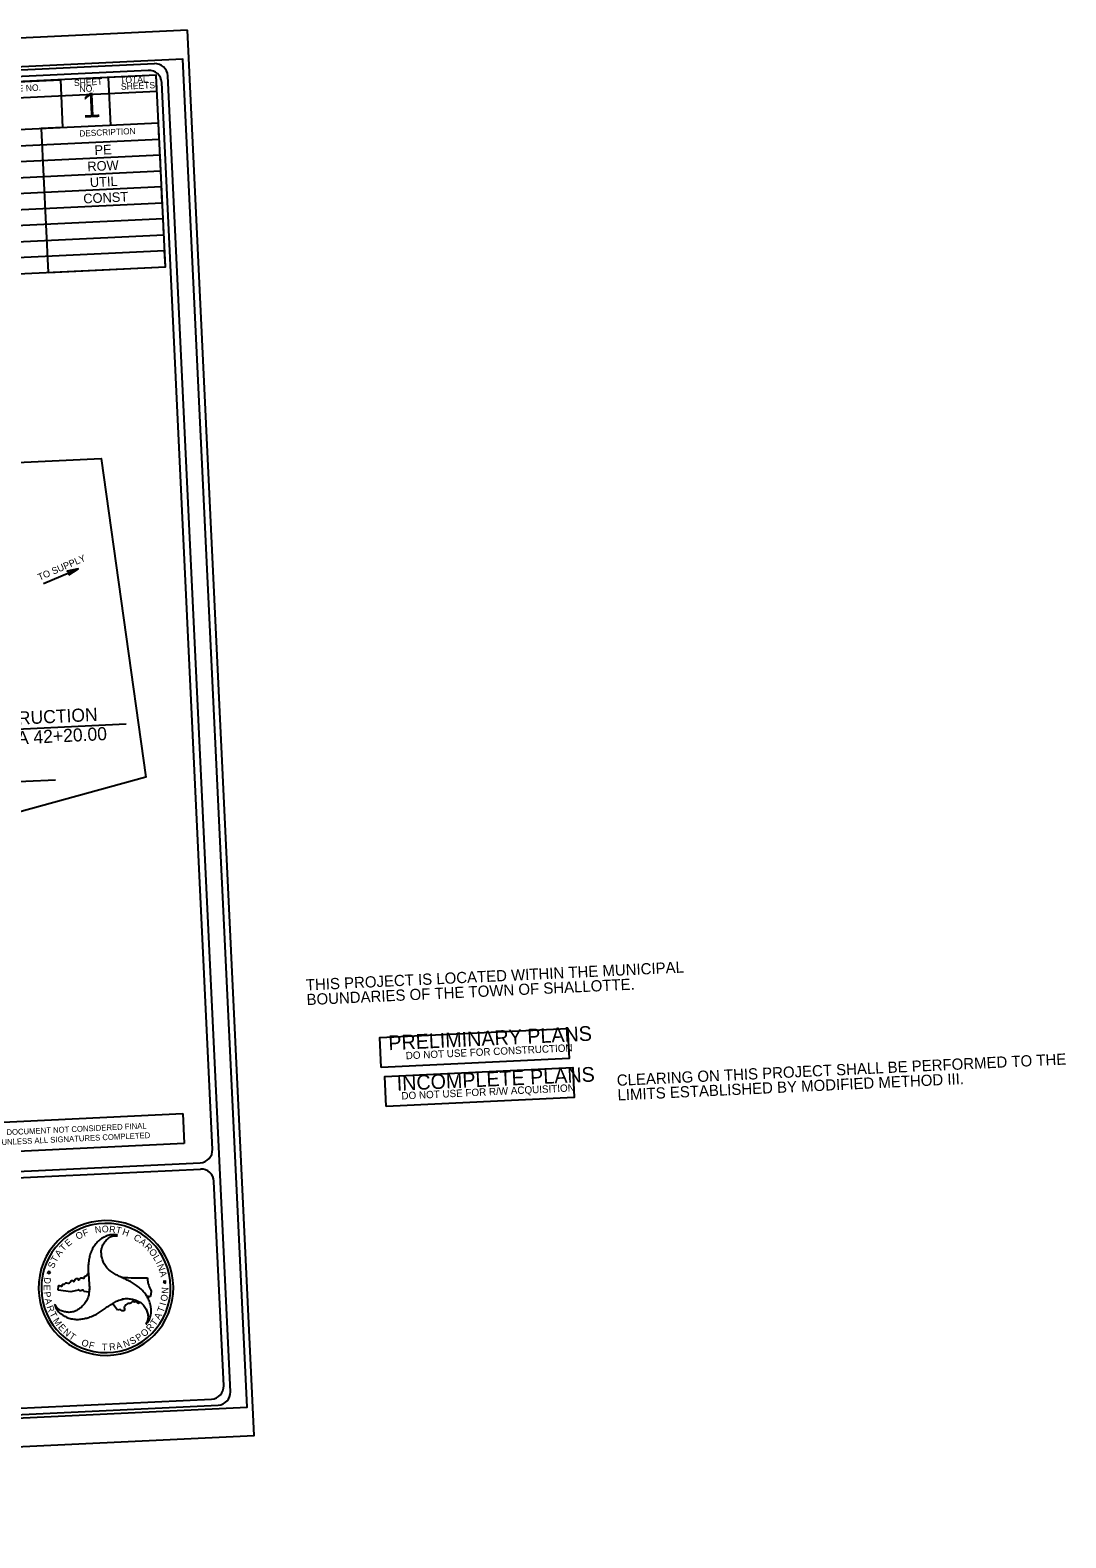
# Model space of a CAD drawing. Extents: x 2170913 to 2188101, y 74009 to 87693.
# Drawn here: x 2182226 to 2188101, y 74009 to 82562 of the extents above; entities that cross this region are included whole.
import ezdxf

# ---------------------------------------------------------------- set-up
doc = ezdxf.new("R2010")
doc.units = 0
for name, color, linetype in [('CTL Primary Horizontal and Vertical CELL', 7, 'Continuous'), ('CTL Primary Horizontal CELL', 7, 'Continuous'), ('CTL Primary Horizontal Cogo Comment', 7, 'Continuous'), ('CTL Primary Horizontal Cogo Number', 7, 'Continuous'), ('Exist Other Culture Sign', 7, 'Continuous'), ('Exist Other Culture Sign Cogo Point CELL', 7, 'Continuous'), ('Exist Property Iron Pin CELL', 7, 'Continuous'), ('Exist Property Iron Pin Cogo Number', 7, 'Continuous'), ('Exist Structure Minor Pipes HDPE 30 Inch', 7, 'Continuous'), ('Exist Utilities Other Traffic Signal Box CELL', 7, 'Continuous')]:
    doc.layers.add(name, color=color, linetype=linetype)

msp = doc.modelspace()

# ---------------------------------------------------------------- linework, layer by layer
at = {"layer": 'CTL Primary Horizontal and Vertical CELL'}
msp.add_lwpolyline([(2183118, 82562.2), (2170912.8, 81981.8), (2171291.9, 74009.3), (2183497.2, 74589.8)], close=True, dxfattribs=at)
at = {"layer": 'CTL Primary Horizontal CELL'}
for p, q in [((2182027.1, 76365.6), (2183092.5, 76416.3)), ((2183092.5, 76416.2), (2183100.6, 76245.8)), ((2183100.6, 76245.9), (2182035.2, 76195.3))]:
    msp.add_line(p, q, dxfattribs=at)
at = {"layer": 'CTL Primary Horizontal Cogo Comment'}
msp.add_lwpolyline([(2171378.4, 74176.5), (2183456.8, 74750.8), (2183093.1, 82397.9), (2171014.8, 81823.6)], close=True, dxfattribs=at)
at = {"layer": 'CTL Primary Horizontal Cogo Number'}
for p, q in [((2172899.3, 75647.6), (2183191.1, 76137)), ((2182067.8, 76047.3), (2183192.8, 76100.8)), ((2182722.4, 75725.3), (2182721.6, 75724.6)), ((2182722.4, 75725.3), (2182721.6, 75724.6)), ((2182330.8, 75517.3), (2182333.1, 75523.2)), ((2182333.1, 75523.2), (2182334.9, 75516.9)), ((2182329.1, 75513.4), (2182324.1, 75517.8)), ((2182324.1, 75517.8), (2182330.8, 75517.3)), ((2182326.7, 75507.3), (2182329.1, 75513.4)), ((2182332.1, 75510.8), (2182326.7, 75507.3)), ((2182337.2, 75506.4), (2182332.1, 75510.8)), ((2182334.9, 75516.9), (2182341.4, 75516.4)), ((2182341.4, 75516.4), (2182335.7, 75512.9)), ((2182335.7, 75512.9), (2182337.2, 75506.4)), ((2182384.7, 75413.8), (2182387.5, 75436.7)), ((2182743.3, 75487.8), (2182743.3, 75487.8)), ((2182987.6, 75463.6), (2182981, 75464.2)), ((2182981, 75464.2), (2182986.1, 75459.9)), ((2182986.1, 75459.9), (2182983.6, 75453.7)), ((2182983.6, 75453.7), (2182989.1, 75457.1)), ((2182990.1, 75469.6), (2182987.6, 75463.6)), ((2182989.1, 75457.1), (2182994, 75452.8)), ((2182991.9, 75463.3), (2182990.1, 75469.6)), ((2182998.3, 75462.9), (2182991.9, 75463.3)), ((2182992.7, 75459.3), (2182998.3, 75462.9)), ((2182994, 75452.8), (2182992.7, 75459.3)), ((2182456.8, 75404.9), (2182384.7, 75413.8)), ((2182499.3, 75413.6), (2182456.8, 75404.9)), ((2182560.9, 75403.3), (2182530.7, 75406.2)), ((2183037.4, 75394.5), (2183037.4, 75394.5)), ((2182721.9, 75300.5), (2182692.9, 75337.9)), ((2182692.9, 75337.9), (2182692.9, 75337.9))]:
    msp.add_line(p, q, dxfattribs=at)
for points in [[(2182931, 82371.7), (2172204.2, 81861.7)], [(2182896.4, 82333.7), (2172604.7, 81844.3)], [(2180952.5, 82121.5), (2182945.6, 82216.3), (2182941.3, 82306.9), (2180948.2, 82212)], [(2181220, 82225.1), (2182397.8, 82281), (2182410.6, 82009.3), (2182289.6, 82003.5), (2182328.4, 81188.1), (2182993, 81219.7), (2182941.3, 82306.9), (2182669.5, 82294), (2182682.5, 82022.2)], [(2183361.9, 74837.6), (2183006.9, 82302.7)], [(2183260.2, 76212.8), (2182972.4, 82264.8)], [(2180965.4, 81849.6), (2182958.5, 81944.4), (2182954.2, 82035.1), (2180961.1, 81940.3)], [(2180974, 81668.5), (2182967.1, 81763.3), (2182962.8, 81853.8), (2180969.7, 81759.1)], [(2180982.6, 81487.4), (2182975.8, 81582.1), (2182971.5, 81672.7), (2180978.3, 81577.9)], [(2180991.3, 81306.1), (2182984.4, 81400.9), (2182980.1, 81491.4), (2180987, 81396.7)], [(2180999.9, 81125), (2182993, 81219.7), (2182988.7, 81310.3), (2180995.6, 81215.6)], [(2183323.9, 74872.1), (2183268.8, 76031.7)], [(2172566.2, 74251.5), (2183292.9, 74761.6)], [(2182129.9, 74742.7), (2183254.9, 74796.2)]]:
    msp.add_lwpolyline(points, dxfattribs=at)
for centre, radius, start, end in [((2182934.4, 82299.6), 72.6, 2.72267, 92.72267), ((2182899.9, 82261.7), 72.6, 2.72267, 92.72267), ((2183187.7, 76209.8), 72.6, 272.72267, 2.72267), ((2183196.3, 76028.6), 72.6, 2.72267, 92.72267), ((2182656.3, 75426.8), 382.5, 355.1438, 175.1438), ((2182656.3, 75426.8), 366.6, 355.1438, 175.1438), ((2182656.3, 75426.8), 382.5, 175.1438, 355.1438), ((2182656.3, 75426.8), 366.6, 175.1438, 355.1438), ((2182874.8, 77500.3), 2016.7, 260.82229, 260.92189), ((2182874.8, 77500.3), 2016.7, 266.26134, 270.46736), ((2183251.5, 74869), 72.6, 272.72267, 2.72267), ((2183289.4, 74834.5), 72.6, 272.72267, 2.72267)]:
    msp.add_arc(centre, radius, start, end, dxfattribs=at)
for points in [[(2182721.6, 75724.6), (2182713.2, 75727.6), (2182687.8, 75728.7), (2182661.4, 75722.7), (2182659, 75721.6), (2182645.6, 75715.9), (2182631, 75706.9), (2182608.7, 75689.1), (2182590.8, 75666.4), (2182583.6, 75656.7), (2182577.9, 75644.4), (2182567.2, 75618.2), (2182560.6, 75592.6), (2182556.3, 75562.4), (2182554.5, 75535.7), (2182556.6, 75508.1), (2182559, 75480.2), (2182560.7, 75453.2), (2182562.1, 75425.5), (2182559.9, 75398.2), (2182559.6, 75395.9), (2182552.2, 75367.3), (2182538.3, 75342.8), (2182521.4, 75322.8), (2182511.6, 75313.7), (2182498, 75304.8), (2182490.3, 75299.7), (2182472.3, 75292.4), (2182445.6, 75288.5), (2182420.2, 75292.1), (2182398.1, 75299.8), (2182379.3, 75314.2), (2182365.2, 75333.9)], [(2182882, 75220.7), (2182888.4, 75226.3), (2182902.3, 75247.7), (2182910.3, 75273.7), (2182910.9, 75276.3), (2182912.3, 75290.8), (2182911.9, 75308), (2182907.9, 75336.2), (2182896.8, 75362.9), (2182892.2, 75374.1), (2182884.3, 75385.4), (2182867.1, 75407.6), (2182848.3, 75426.2), (2182824.2, 75444.9), (2182801.9, 75459.6), (2182776.9, 75472), (2182751.7, 75483.7), (2182727.7, 75495.6), (2182702.5, 75508.4), (2182680.2, 75523.9), (2182678.4, 75525.5), (2182657, 75546.2), (2182642.9, 75570.5), (2182633.8, 75595.1), (2182631.3, 75607.9), (2182630.4, 75624.3), (2182629.5, 75633.7), (2182632.5, 75652.7), (2182642.3, 75678), (2182658, 75697.9), (2182675.8, 75713.1), (2182697.9, 75722.2), (2182721.6, 75724.6), (2182722.4, 75725.3)], [(2182387.5, 75436.7), (2182386.8, 75438.9), (2182390.9, 75441), (2182401.3, 75435.7), (2182407.1, 75439.9), (2182407.2, 75444.5), (2182411.9, 75448.8), (2182419.1, 75446.7), (2182426.5, 75454.6), (2182432.8, 75455.6), (2182445.6, 75454.5), (2182462.2, 75468.5), (2182468.7, 75468.9), (2182469.9, 75464.7), (2182473.8, 75463.6), (2182481.5, 75475.7), (2182483.3, 75477.3), (2182495.7, 75481.1), (2182498.7, 75478.5), (2182499.1, 75472.8), (2182500.7, 75471.5), (2182504.9, 75474), (2182510.8, 75480.4), (2182521, 75484.6), (2182532.1, 75482.3), (2182534.8, 75491.3), (2182548.6, 75499), (2182551.8, 75504.1), (2182552.9, 75509.4)], [(2182556.5, 75508.8), (2182556.6, 75508.1), (2182559, 75480.2), (2182560.7, 75453.2), (2182562.1, 75425.5), (2182560.8, 75403.3)], [(2182889.7, 75378.4), (2182884.3, 75385.4), (2182867.1, 75407.6), (2182848.3, 75426.2), (2182824.2, 75444.9), (2182801.9, 75459.6), (2182776.9, 75472), (2182751.7, 75483.7), (2182743.3, 75487.8)], [(2182891.2, 75483.5), (2182894.4, 75457.7), (2182905.2, 75426.6), (2182912.4, 75409.5), (2182911, 75395.4), (2182906.3, 75378.8), (2182889.9, 75378.5)], [(2182365.2, 75333.9), (2182367.2, 75325.1), (2182378.8, 75302.5), (2182397.1, 75282.5), (2182399.2, 75281.2), (2182411, 75272.1), (2182426.1, 75264.2), (2182452.7, 75253.5), (2182481, 75249.7), (2182493.1, 75248.1), (2182507.2, 75249.5), (2182534.6, 75253.3), (2182560, 75260.1), (2182588.5, 75271.7), (2182612.2, 75283.4), (2182635.4, 75299.1), (2182658.2, 75315.2), (2182680.8, 75330), (2182704.3, 75345), (2182728.9, 75356.9), (2182731.5, 75357.7), (2182760, 75365.8), (2182787.8, 75365.9), (2182813.3, 75361.5), (2182826.5, 75357.5), (2182840.6, 75349.8), (2182849.4, 75346), (2182864.5, 75333.9), (2182881, 75312.8), (2182890.6, 75289.2), (2182895, 75266), (2182891.9, 75242.5), (2182882, 75220.7)], [(2182530.7, 75406.2), (2182528.3, 75412), (2182522.5, 75414.2), (2182514.3, 75410.6), (2182508.3, 75411.5), (2182502.2, 75416.8), (2182499.3, 75413.6)], [(2182692.9, 75337.9), (2182704.3, 75345), (2182728.9, 75356.9), (2182731.5, 75357.7), (2182760, 75365.8), (2182787.8, 75365.9), (2182813.3, 75361.5), (2182826.5, 75357.5), (2182840.6, 75349.8), (2182848.8, 75346.2)], [(2182848.7, 75346.1), (2182844.6, 75339.7), (2182838.8, 75339.7), (2182829.4, 75348.6), (2182816.9, 75347.2), (2182811.5, 75350.9), (2182807.8, 75351.3), (2182797.9, 75340.9), (2182785.5, 75339.2), (2182764.5, 75326.4), (2182759.7, 75318.2), (2182759.6, 75299.8), (2182754.5, 75296.6), (2182748.7, 75298), (2182736.9, 75303.8), (2182721.9, 75300.5)]]:
    msp.add_spline(points, degree=3, dxfattribs=at)
at = {"layer": 'Exist Other Culture Sign'}
msp.add_lwpolyline([(2184246.5, 76457), (2184238.4, 76627.3), (2185303.9, 76678), (2185312, 76507.7)], close=True, dxfattribs=at)
at = {"layer": 'Exist Property Iron Pin CELL'}
for p, q in [((2182301.7, 79422.8), (2182498.3, 79506.7)), ((2182770.5, 78624.8), (2181526.2, 78565.6)), ((2182369.8, 78308.4), (2180865.5, 78236.8))]:
    msp.add_line(p, q, dxfattribs=at)
at = {"layer": 'Exist Property Iron Pin Cogo Number'}
msp.add_lwpolyline([(2182445.3, 79472.9), (2182498.3, 79506.7), (2182436.6, 79492.7), (2182448.2, 79485.7)], close=True, dxfattribs=at)
at = {"layer": 'Exist Structure Minor Pipes HDPE 30 Inch'}
msp.add_lwpolyline([(2177668.6, 79896.6), (2182629.7, 80132.5), (2182882.8, 78325.4), (2178890.9, 77226), (2178290.9, 78673.1), (2177852.1, 79004.7), (2177687.9, 79128.8)], close=True, dxfattribs=at)
at = {"layer": 'Exist Utilities Other Traffic Signal Box CELL'}
msp.add_lwpolyline([(2184217.5, 76677.7), (2184209.4, 76848.1), (2185274.8, 76898.7), (2185282.9, 76728.4)], close=True, dxfattribs=at)

# ---------------------------------------------------------------- texts
at = {"layer": 'CTL Primary Horizontal CELL'}
for s, p in [('UNLESS ALL SIGNATURES COMPLETED', (2182064.6, 76237.4)), ('DOCUMENT NOT CONSIDERED FINAL', (2182092.6, 76293.6))]:
    msp.add_text(s, height=32.652, rotation=2.72267, dxfattribs=at).set_placement(p)
at = {"layer": 'CTL Primary Horizontal Cogo Number'}
for s, height, rotation, p in [('SHEET', 36.28, 2.72267, (2182475.4, 82244.7)), ('TOTAL', 36.28, 2.72267, (2182737.6, 82259.8)), ('STATE PROJECT REFERENCE NO.', 36.278, 2.72267, (2181480.6, 82181.1)), ('NO.', 36.28, 2.72267, (2182507.1, 82210.4)), ('1', 140.4, 2.72267, (2182523.2, 82064.4)), ('SHEETS', 36.28, 2.72267, (2182741.8, 82223.7)), ('DESCRIPTION', 34.829, 2.72267, (2182506.4, 81958.2)), ('N', 38.2, 8.12757, (2182595.5, 75736.9)), ('O', 38.2, 0.62947, (2182632.4, 75742)), ('R', 38.1, 354.01954, (2182672.7, 75742.4)), ('E', 38, 39.30074, (2182441.7, 75658.8)), ('O', 38.2, 27.36136, (2182496.1, 75699)), ('F', 38.2, 20.21452, (2182532, 75717.4)), ('T', 38.2, 347.36991, (2182709.1, 75738.6)), ('H', 38.1, 340.28519, (2182745.4, 75730.2)), ('C', 38, 327.94284, (2182809.2, 75703.6)), ('A', 38.1, 320.44581, (2182841.3, 75683.2)), ('T', 38.2, 60.52389, (2182373.6, 75568)), ('A', 38.3, 53.47158, (2182392.4, 75600.2)), ('T', 38, 46.41636, (2182415.9, 75631.9)), ('R', 38.1, 314.08186, (2182871.5, 75658.4)), ('O', 38.2, 306.96226, (2182896.9, 75632.1)), ('L', 38, 300.72858, (2182921.3, 75599.6)), ('S', 38.1, 66.90005, (2182359.3, 75534.6)), ('I', 38.2, 296.73924, (2182937.5, 75571)), ('N', 38.1, 291.03913, (2182945.6, 75554.2)), ('E', 38, 269.28469, (2182302.6, 75445.5)), ('D', 38.1, 262.9968, (2182307.6, 75489)), ('A', 38.1, 283.60716, (2182958.8, 75519.2)), ('P', 38.1, 276.81708, (2182302.9, 75404)), ('A', 38.1, 283.40965, (2182307.7, 75363.6)), ('O', 38, 80.10391, (2183002, 75348.3)), ('N', 38.1, 87.35193, (2183009.5, 75393.7)), ('R', 38.1, 290.47829, (2182318.7, 75319.7)), ('T', 38.1, 297.12882, (2182333.8, 75280.5)), ('A', 38.2, 62.23396, (2182960.2, 75244)), ('T', 38.1, 69.31838, (2182980.8, 75284.2)), ('I', 38.2, 74.96829, (2182995.9, 75324.6)), ('M', 38, 304.36386, (2182354.1, 75242.2)), ('E', 38, 311.83064, (2182382.1, 75202.6)), ('N', 38.2, 318.80218, (2182409.9, 75172.3)), ('O', 38.2, 40.85802, (2182873, 75146.3)), ('R', 38.2, 48.04712, (2182907.7, 75176.7)), ('T', 38, 54.14691, (2182935.5, 75208.5)), ('T', 38.1, 325.64418, (2182442.6, 75144.2)), ('O', 38.1, 338.94787, (2182512.7, 75102.9)), ('F', 38.1, 346.11309, (2182555.9, 75086.9)), ('T', 38, 359.02232, (2182632.7, 75073.1)), ('R', 38.2, 5.97894, (2182675.9, 75072.9)), ('A', 38, 12.73207, (2182717.8, 75077.8)), ('N', 38, 19.76371, (2182761.6, 75088.5)), ('S', 38, 26.97418, (2182801.9, 75103.8)), ('P', 38.1, 34.16603, (2182839.4, 75123.1))]:
    msp.add_text(s, height=height, rotation=rotation, dxfattribs=at).set_placement(p)
at = {"layer": 'Exist Other Culture Sign'}
for s, height, p in [('INCOMPLETE PLANS', 83.588, (2184307.4, 76544.9)), ('DO NOT USE FOR R/W ACQUISITION', 41.794, (2184333.3, 76495.6))]:
    msp.add_text(s, height=height, rotation=2.72267, dxfattribs=at).set_placement(p)
at = {"layer": 'Exist Other Culture Sign Cogo Point CELL'}
for s, height, p in [('PE', 54.42, (2182592.5, 81854)), ('ROW', 54.42, (2182551.9, 81761.4)), ('UTIL      ', 54.42, (2182566.1, 81671.3)), ('CONST     ', 54.42, (2182528.9, 81578.8)), ('THIS PROJECT IS LOCATED WITHIN THE MUNICIPAL', 63.491, (2183791.7, 77114.2)), ('BOUNDARIES OF THE TOWN OF SHALLOTTE.', 63.491, (2183795.6, 77031)), ('CLEARING ON THIS PROJECT SHALL BE PERFORMED TO THE ', 63.491, (2185555.4, 76573.1)), ('LIMITS ESTABLISHED BY MODIFIED METHOD III.', 63.491, (2185559.4, 76490))]:
    msp.add_text(s, height=height, rotation=2.72267, dxfattribs=at).set_placement(p)
at = {"layer": 'Exist Property Iron Pin CELL'}
for s, height, rotation, p in [('TO SUPPLY', 38.53, 23.34216, (2182279.3, 79439)), ('END CONSTRUCTION', 74.313, 2.80128, (2181573.9, 78593.6)), ('-L1- POC STA 42+20.00', 74.313, 2.80128, (2181579.3, 78482.3))]:
    msp.add_text(s, height=height, rotation=rotation, dxfattribs=at).set_placement(p)
at = {"layer": 'Exist Utilities Other Traffic Signal Box CELL'}
for s, height, p in [('PRELIMINARY PLANS', 83.588, (2184260.1, 76775.3)), ('DO NOT USE FOR CONSTRUCTION', 41.794, (2184357.7, 76724))]:
    msp.add_text(s, height=height, rotation=2.72267, dxfattribs=at).set_placement(p)

doc.saveas('drawing.dxf')
